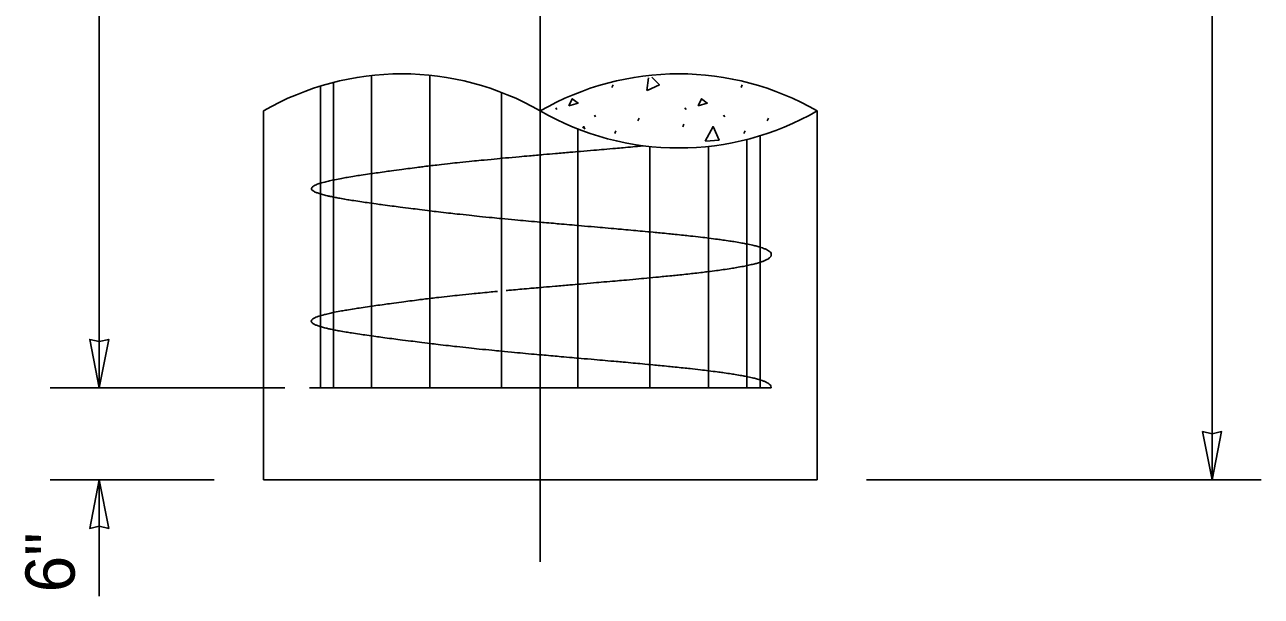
# Model space of a CAD drawing. Extents: x 99888 to 103177, y 100000 to 102076.
# Drawn here: x 101642.6 to 102044.5, y 100377.5 to 100563.3 of the extents above; entities that cross this region are included whole.
import ezdxf

# ---------------------------------------------------------------- set-up
doc = ezdxf.new("R2010")
doc.units = 0
for name, color, linetype in [('Level 10', 7, 'Continuous'), ('Level 15', 7, 'Continuous'), ('Level 2', 7, 'Continuous'), ('Level 20', 7, 'Continuous'), ('Level 23', 7, 'Continuous')]:
    doc.layers.add(name, color=color, linetype=linetype)

msp = doc.modelspace()

# ---------------------------------------------------------------- linework, layer by layer
at = {"layer": 'Level 10'}
for p, q in [((101755.28, 100546.79), (101755.28, 100445.28)), ((101755.28, 100546.79), (101755.28, 100445.28)), ((101774.26, 100546.87), (101774.26, 100445.28)), ((101774.26, 100546.87), (101774.26, 100445.28)), ((101738.66, 100543.35), (101738.66, 100445.28)), ((101738.66, 100543.35), (101738.66, 100445.28)), ((101742.92, 100544.55), (101742.92, 100445.28)), ((101742.92, 100544.55), (101742.92, 100445.28)), ((101797.57, 100541.29), (101797.57, 100445.28)), ((101797.57, 100541.29), (101797.57, 100445.28)), ((101822.39, 100529.39), (101822.39, 100445.28)), ((101822.39, 100529.39), (101822.39, 100445.28)), ((101877.24, 100525.98), (101877.24, 100445.28)), ((101877.24, 100525.98), (101877.24, 100445.28)), ((101881.61, 100527.2), (101881.61, 100445.28)), ((101881.61, 100527.2), (101881.61, 100445.28)), ((101845.74, 100523.71), (101845.74, 100445.28)), ((101845.74, 100523.71), (101845.74, 100445.28)), ((101864.79, 100523.74), (101864.79, 100445.28)), ((101864.79, 100523.74), (101864.79, 100445.28)), ((101885.13, 100445.28), (101735.13, 100445.28)), ((101885.13, 100445.28), (101735.13, 100445.28))]:
    msp.add_line(p, q, dxfattribs=at)
for points in [[(101843.84, 100523.93), (101842.13, 100523.77), (101840.39, 100523.61), (101836.82, 100523.29), (101835, 100523.13), (101830.57, 100522.74), (101827.94, 100522.52), (101822.8, 100522.07), (101820.3, 100521.86), (101814.7, 100521.38), (101811.61, 100521.11), (101806.1, 100520.62), (101803.7, 100520.41), (101798.4, 100519.93), (101795.52, 100519.66), (101790.49, 100519.17), (101788.33, 100518.96), (101783.64, 100518.48), (101781.13, 100518.21), (101776.8, 100517.72), (101774.98, 100517.51), (101772.08, 100517.15), (101770.98, 100517.02), (101767.6, 100516.57), (101765.39, 100516.28), (101761.45, 100515.75), (101759.7, 100515.51), (101756.46, 100515.06), (101754.96, 100514.84), (101751.69, 100514.35), (101749.98, 100514.09), (101747.07, 100513.61), (101745.85, 100513.39), (101743.14, 100512.88), (101741.76, 100512.59), (101739.84, 100512.11), (101739.18, 100511.93), (101738.13, 100511.6), (101737.72, 100511.46), (101736.9, 100511.12), (101736.54, 100510.92), (101736.06, 100510.57), (101735.91, 100510.41), (101735.75, 100510.05), (101735.78, 100509.85), (101736.05, 100509.48), (101736.24, 100509.32), (101736.8, 100508.99), (101737.17, 100508.81), (101738.34, 100508.37), (101739.24, 100508.1), (101740.98, 100507.67), (101741.69, 100507.51), (101743.54, 100507.12), (101744.75, 100506.89), (101747.28, 100506.45), (101748.6, 100506.24), (101751.72, 100505.76), (101753.56, 100505.49), (101757.06, 100505), (101758.64, 100504.79), (101762.24, 100504.32), (101764.26, 100504.06), (101768.43, 100503.53), (101770.58, 100503.26), (101774.7, 100502.74), (101776.66, 100502.5), (101780.65, 100502.03), (101782.68, 100501.8), (101787.36, 100501.29), (101790.02, 100501.01), (101794.92, 100500.52), (101797.14, 100500.31), (101802.25, 100499.82), (101805.14, 100499.55), (101809.56, 100499.15), (101811.07, 100499.02), (101814.63, 100498.7), (101816.66, 100498.52), (101820.87, 100498.15), (101823.03, 100497.97), (101828.13, 100497.52), (101831.04, 100497.26), (101835.34, 100496.88), (101836.76, 100496.76), (101840.66, 100496.41), (101843.1, 100496.18), (101847.19, 100495.8), (101848.87, 100495.63), (101852.14, 100495.31), (101853.74, 100495.15), (101856.96, 100494.81), (101858.58, 100494.64), (101862.52, 100494.2), (101864.75, 100493.93), (101868.07, 100493.5), (101869.25, 100493.34), (101871.93, 100492.95), (101873.38, 100492.72), (101875.93, 100492.28), (101877.05, 100492.07), (101879.32, 100491.59), (101880.4, 100491.32), (101882.03, 100490.83), (101882.65, 100490.62), (101883.77, 100490.14), (101884.24, 100489.88), (101885, 100489.29), (101885.21, 100488.94), (101885.21, 100488.4)], [(101843.84, 100523.93), (101842.13, 100523.77), (101840.39, 100523.61), (101836.82, 100523.29), (101835, 100523.13), (101830.57, 100522.74), (101827.94, 100522.52), (101822.8, 100522.07), (101820.3, 100521.86), (101814.7, 100521.38), (101811.61, 100521.11), (101806.1, 100520.62), (101803.7, 100520.41), (101798.4, 100519.93), (101795.52, 100519.66), (101790.49, 100519.17), (101788.33, 100518.96), (101783.64, 100518.48), (101781.13, 100518.21), (101776.8, 100517.72), (101774.98, 100517.51), (101772.08, 100517.15), (101770.98, 100517.02), (101767.6, 100516.57), (101765.39, 100516.28), (101761.45, 100515.75), (101759.7, 100515.51), (101756.46, 100515.06), (101754.96, 100514.84), (101751.69, 100514.35), (101749.98, 100514.09), (101747.07, 100513.61), (101745.85, 100513.39), (101743.14, 100512.88), (101741.76, 100512.59), (101739.84, 100512.11), (101739.18, 100511.93), (101738.13, 100511.6), (101737.72, 100511.46), (101736.9, 100511.12), (101736.54, 100510.92), (101736.06, 100510.57), (101735.91, 100510.41), (101735.75, 100510.05), (101735.78, 100509.85), (101736.05, 100509.48), (101736.24, 100509.32), (101736.8, 100508.99), (101737.17, 100508.81), (101738.34, 100508.37), (101739.24, 100508.1), (101740.98, 100507.67), (101741.69, 100507.51), (101743.54, 100507.12), (101744.75, 100506.89), (101747.28, 100506.45), (101748.6, 100506.24), (101751.72, 100505.76), (101753.56, 100505.49), (101757.06, 100505), (101758.64, 100504.79), (101762.24, 100504.32), (101764.26, 100504.06), (101768.43, 100503.53), (101770.58, 100503.26), (101774.7, 100502.74), (101776.66, 100502.5), (101780.65, 100502.03), (101782.68, 100501.8), (101787.36, 100501.29), (101790.02, 100501.01), (101794.92, 100500.52), (101797.14, 100500.31), (101802.25, 100499.82), (101805.14, 100499.55), (101809.56, 100499.15), (101811.07, 100499.02), (101814.63, 100498.7), (101816.66, 100498.52), (101820.87, 100498.15), (101823.03, 100497.97), (101828.13, 100497.52), (101831.04, 100497.26), (101835.34, 100496.88), (101836.76, 100496.76), (101840.66, 100496.41), (101843.1, 100496.18), (101847.19, 100495.8), (101848.87, 100495.63), (101852.14, 100495.31), (101853.74, 100495.15), (101856.96, 100494.81), (101858.58, 100494.64), (101862.52, 100494.2), (101864.75, 100493.93), (101868.07, 100493.5), (101869.25, 100493.34), (101871.93, 100492.95), (101873.38, 100492.72), (101875.93, 100492.28), (101877.05, 100492.07), (101879.32, 100491.59), (101880.4, 100491.32), (101882.03, 100490.83), (101882.65, 100490.62), (101883.77, 100490.14), (101884.24, 100489.88), (101885, 100489.29), (101885.21, 100488.94), (101885.21, 100488.4)], [(101885.21, 100488.4), (101885.2, 100488.36), (101885.2, 100488.32), (101885.15, 100488.14), (101885.07, 100487.99), (101884.84, 100487.7), (101884.7, 100487.56), (101884.24, 100487.19), (101883.88, 100486.98), (101882.86, 100486.49), (101882.14, 100486.22), (101880.57, 100485.74), (101879.76, 100485.53), (101877.68, 100485.04), (101876.37, 100484.77), (101873.68, 100484.29), (101872.36, 100484.08), (101869.34, 100483.62), (101867.6, 100483.38), (101864.48, 100482.98), (101863.16, 100482.82), (101860.12, 100482.46), (101858.38, 100482.27), (101855.18, 100481.93), (101853.75, 100481.78), (101850.66, 100481.47), (101848.98, 100481.3), (101844.45, 100480.87), (101841.54, 100480.6), (101836.75, 100480.17), (101834.93, 100480.01), (101830.49, 100479.62), (101827.87, 100479.39), (101822.72, 100478.95), (101820.23, 100478.74), (101814.63, 100478.26), (101811.53, 100477.99), (101806.02, 100477.5), (101803.62, 100477.29), (101800.49, 100477), (101799.74, 100476.94), (101799, 100476.87)], [(101885.21, 100488.4), (101885.2, 100488.36), (101885.2, 100488.32), (101885.15, 100488.14), (101885.07, 100487.99), (101884.84, 100487.7), (101884.7, 100487.56), (101884.24, 100487.19), (101883.88, 100486.98), (101882.86, 100486.49), (101882.14, 100486.22), (101880.57, 100485.74), (101879.76, 100485.53), (101877.68, 100485.04), (101876.37, 100484.77), (101873.68, 100484.29), (101872.36, 100484.08), (101869.34, 100483.62), (101867.6, 100483.38), (101864.48, 100482.98), (101863.16, 100482.82), (101860.12, 100482.46), (101858.38, 100482.27), (101855.18, 100481.93), (101853.75, 100481.78), (101850.66, 100481.47), (101848.98, 100481.3), (101844.45, 100480.87), (101841.54, 100480.6), (101836.75, 100480.17), (101834.93, 100480.01), (101830.49, 100479.62), (101827.87, 100479.39), (101822.72, 100478.95), (101820.23, 100478.74), (101814.63, 100478.26), (101811.53, 100477.99), (101806.02, 100477.5), (101803.62, 100477.29), (101800.49, 100477), (101799.74, 100476.94), (101799, 100476.87)], [(101796.22, 100476.61), (101795.01, 100476.49), (101793.8, 100476.38), (101790.41, 100476.05), (101788.26, 100475.84), (101783.56, 100475.36), (101781.05, 100475.09), (101776.73, 100474.6), (101774.9, 100474.39), (101772, 100474.03), (101770.91, 100473.89), (101767.53, 100473.45), (101765.31, 100473.16), (101761.37, 100472.63), (101759.63, 100472.39), (101756.38, 100471.93), (101754.88, 100471.72), (101751.61, 100471.23), (101749.9, 100470.97), (101747, 100470.48), (101745.77, 100470.27), (101743.07, 100469.76), (101741.69, 100469.46), (101739.77, 100468.99), (101739.11, 100468.81), (101738.06, 100468.48), (101737.64, 100468.33), (101736.82, 100467.99), (101736.46, 100467.8), (101735.98, 100467.45), (101735.84, 100467.29), (101735.68, 100466.93), (101735.71, 100466.72), (101735.97, 100466.36), (101736.16, 100466.2), (101736.72, 100465.86), (101737.1, 100465.69), (101738.26, 100465.25), (101739.16, 100464.98), (101740.9, 100464.55), (101741.61, 100464.39), (101743.47, 100464), (101744.67, 100463.77), (101747.21, 100463.33), (101748.52, 100463.12), (101751.64, 100462.64), (101753.49, 100462.37), (101756.98, 100461.88), (101758.57, 100461.67), (101762.16, 100461.19), (101764.18, 100460.93), (101768.36, 100460.41), (101770.5, 100460.14), (101774.63, 100459.62), (101776.58, 100459.38), (101780.58, 100458.91), (101782.61, 100458.68), (101787.28, 100458.17), (101789.94, 100457.89), (101794.84, 100457.4), (101797.06, 100457.18), (101802.17, 100456.7), (101805.07, 100456.43), (101809.49, 100456.03), (101811, 100455.9), (101814.55, 100455.58), (101816.59, 100455.4), (101820.79, 100455.03), (101822.95, 100454.84), (101828.06, 100454.4), (101830.97, 100454.14), (101835.27, 100453.76), (101836.68, 100453.64), (101840.59, 100453.28), (101843.03, 100453.06), (101847.12, 100452.67), (101848.79, 100452.51), (101852.07, 100452.19), (101853.66, 100452.03), (101856.89, 100451.69), (101858.51, 100451.52), (101862.45, 100451.08), (101864.68, 100450.81), (101868, 100450.38), (101869.18, 100450.22), (101871.86, 100449.83), (101873.3, 100449.6), (101875.86, 100449.16), (101876.98, 100448.94), (101879.24, 100448.46), (101880.32, 100448.19), (101881.96, 100447.71), (101882.57, 100447.5), (101883.69, 100447.02), (101884.16, 100446.76), (101884.92, 100446.16), (101885.13, 100445.82), (101885.13, 100445.28)], [(101796.22, 100476.61), (101795.01, 100476.49), (101793.8, 100476.38), (101790.41, 100476.05), (101788.26, 100475.84), (101783.56, 100475.36), (101781.05, 100475.09), (101776.73, 100474.6), (101774.9, 100474.39), (101772, 100474.03), (101770.91, 100473.89), (101767.53, 100473.45), (101765.31, 100473.16), (101761.37, 100472.63), (101759.63, 100472.39), (101756.38, 100471.93), (101754.88, 100471.72), (101751.61, 100471.23), (101749.9, 100470.97), (101747, 100470.48), (101745.77, 100470.27), (101743.07, 100469.76), (101741.69, 100469.46), (101739.77, 100468.99), (101739.11, 100468.81), (101738.06, 100468.48), (101737.64, 100468.33), (101736.82, 100467.99), (101736.46, 100467.8), (101735.98, 100467.45), (101735.84, 100467.29), (101735.68, 100466.93), (101735.71, 100466.72), (101735.97, 100466.36), (101736.16, 100466.2), (101736.72, 100465.86), (101737.1, 100465.69), (101738.26, 100465.25), (101739.16, 100464.98), (101740.9, 100464.55), (101741.61, 100464.39), (101743.47, 100464), (101744.67, 100463.77), (101747.21, 100463.33), (101748.52, 100463.12), (101751.64, 100462.64), (101753.49, 100462.37), (101756.98, 100461.88), (101758.57, 100461.67), (101762.16, 100461.19), (101764.18, 100460.93), (101768.36, 100460.41), (101770.5, 100460.14), (101774.63, 100459.62), (101776.58, 100459.38), (101780.58, 100458.91), (101782.61, 100458.68), (101787.28, 100458.17), (101789.94, 100457.89), (101794.84, 100457.4), (101797.06, 100457.18), (101802.17, 100456.7), (101805.07, 100456.43), (101809.49, 100456.03), (101811, 100455.9), (101814.55, 100455.58), (101816.59, 100455.4), (101820.79, 100455.03), (101822.95, 100454.84), (101828.06, 100454.4), (101830.97, 100454.14), (101835.27, 100453.76), (101836.68, 100453.64), (101840.59, 100453.28), (101843.03, 100453.06), (101847.12, 100452.67), (101848.79, 100452.51), (101852.07, 100452.19), (101853.66, 100452.03), (101856.89, 100451.69), (101858.51, 100451.52), (101862.45, 100451.08), (101864.68, 100450.81), (101868, 100450.38), (101869.18, 100450.22), (101871.86, 100449.83), (101873.3, 100449.6), (101875.86, 100449.16), (101876.98, 100448.94), (101879.24, 100448.46), (101880.32, 100448.19), (101881.96, 100447.71), (101882.57, 100447.5), (101883.69, 100447.02), (101884.16, 100446.76), (101884.92, 100446.16), (101885.13, 100445.82), (101885.13, 100445.28)]]:
    msp.add_open_spline(points, degree=3, dxfattribs=at)
at = {"layer": 'Level 15'}
for p, q in [((101666.8, 100445.28), (101666.8, 101195.28)), ((101666.8, 100445.28), (101666.8, 101195.28)), ((102028.47, 100415.28), (102028.47, 100899.75)), ((102028.47, 100415.28), (102028.47, 100887.75)), ((101810.13, 100388.61), (101810.13, 100877.83)), ((101727.13, 100445.28), (101650.8, 100445.28)), ((101727.13, 100445.28), (101650.8, 100445.28)), ((101704.13, 100415.28), (101650.8, 100415.28)), ((101704.13, 100415.28), (101650.8, 100415.28)), ((101666.8, 100415.28), (101666.8, 100377.46)), ((101666.8, 100415.28), (101666.8, 100377.46)), ((101916.13, 100415.28), (102044.47, 100415.28)), ((101916.13, 100415.28), (102044.47, 100415.28))]:
    msp.add_line(p, q, dxfattribs=at)
for points in [[(101666.8, 100445.28), (101663.72, 100461), (101666.8, 100460.27), (101669.88, 100461)], [(101666.8, 100445.28), (101663.72, 100461), (101666.8, 100460.27), (101669.88, 100461)], [(102028.47, 100415.28), (102025.39, 100431), (102028.47, 100430.27), (102031.56, 100431)], [(102028.47, 100415.28), (102025.39, 100431), (102028.47, 100430.27), (102031.56, 100431)], [(101666.8, 100415.28), (101663.72, 100399.55), (101666.8, 100400.28), (101669.88, 100399.55)], [(101666.8, 100415.28), (101663.72, 100399.55), (101666.8, 100400.28), (101669.88, 100399.55)]]:
    msp.add_lwpolyline(points, close=True, dxfattribs=at)
at = {"layer": 'Level 2'}
for p, q in [((101720.13, 100415.28), (101720.13, 100535.28)), ((101720.13, 100415.28), (101720.13, 100535.28)), ((101900.13, 100415.28), (101900.13, 100535.28)), ((101900.13, 100415.28), (101900.13, 100535.28)), ((101720.13, 100415.28), (101900.13, 100415.28)), ((101720.13, 100415.28), (101900.13, 100415.28))]:
    msp.add_line(p, q, dxfattribs=at)
for centre, start, end in [((101765.13, 100457.33), 60, 120), ((101765.13, 100457.33), 60, 120), ((101855.13, 100457.33), 60, 120), ((101855.13, 100457.33), 60, 120), ((101855.13, 100613.22), 240, 300), ((101855.13, 100613.22), 240, 300)]:
    msp.add_arc(centre, 90, start, end, dxfattribs=at)
at = {"layer": 'Level 23'}
for p, q in [((101833.41, 100542.86), (101833.78, 100543.7)), ((101833.41, 100542.86), (101833.78, 100543.7)), ((101875.41, 100542.86), (101875.78, 100543.7)), ((101875.41, 100542.86), (101875.78, 100543.7)), ((101815.15, 100536.24), (101815.52, 100535.68)), ((101815.15, 100536.24), (101815.52, 100535.68)), ((101827.71, 100533.87), (101828.08, 100533.31)), ((101827.71, 100533.87), (101828.08, 100533.31)), ((101857.15, 100536.24), (101857.52, 100535.68)), ((101857.15, 100536.24), (101857.52, 100535.68)), ((101869.71, 100533.87), (101870.08, 100533.31)), ((101869.71, 100533.87), (101870.08, 100533.31)), ((101841.89, 100532.04), (101842.27, 100532.88)), ((101841.89, 100532.04), (101842.27, 100532.88)), ((101856.44, 100530.1), (101856.82, 100530.94)), ((101856.44, 100530.1), (101856.82, 100530.94)), ((101883.89, 100532.04), (101884.27, 100532.88)), ((101883.89, 100532.04), (101884.27, 100532.88)), ((101834.34, 100527.95), (101834.71, 100528.79)), ((101834.34, 100527.95), (101834.71, 100528.79)), ((101876.34, 100527.95), (101876.71, 100528.79)), ((101876.34, 100527.95), (101876.71, 100528.79))]:
    msp.add_line(p, q, dxfattribs=at)
for points in [[(101844.75, 100541.9), (101845.33, 100546.07)], [(101844.75, 100541.9), (101845.33, 100546.07)], [(101846.44, 100546.25), (101848.83, 100543.77), (101844.84, 100541.93)], [(101846.44, 100546.25), (101848.83, 100543.77), (101844.84, 100541.93)], [(101819.42, 100536.89), (101820.54, 100539.22), (101822.41, 100537.82), (101819.42, 100536.89)], [(101819.42, 100536.89), (101820.54, 100539.22), (101822.41, 100537.82), (101819.42, 100536.89)], [(101861.42, 100536.89), (101862.54, 100539.22), (101864.41, 100537.82), (101861.42, 100536.89)], [(101861.42, 100536.89), (101862.54, 100539.22), (101864.41, 100537.82), (101861.42, 100536.89)], [(101823.98, 100529.64), (101824.27, 100530.19), (101824.64, 100529.37)], [(101823.98, 100529.64), (101824.27, 100530.19), (101824.64, 100529.37)], [(101863.75, 100525.44), (101866.27, 100530.19), (101868.23, 100525.81), (101863.85, 100525.44)], [(101863.75, 100525.44), (101866.27, 100530.19), (101868.23, 100525.81), (101863.85, 100525.44)]]:
    msp.add_lwpolyline(points, dxfattribs=at)

# ---------------------------------------------------------------- texts
at = {"layer": 'Level 20'}
msp.add_text('6"', height=16, rotation=90, dxfattribs=at).set_placement((101658.8, 100378.73))
msp.add_text('6"', height=16, rotation=90, dxfattribs=at).set_placement((101658.8, 100378.73))

doc.saveas('drawing.dxf')
